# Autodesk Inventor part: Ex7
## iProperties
Author: Administrator
Created: 2001-01
Part Number: Ex7
Document SubType Name: Modeling
Designer: Administrator
Control State: 0
Master: False
Checked Out: False
PropertySet Name: Design Tracking Control
Shininess: 0.0
PropertySet Name: _Private Model Information
Density: 0.0
Volumn: 0.0
Area: 0.0
PropertySet Name: Model Information
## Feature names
1. Extrusion1
2. Extrusion2
3. Fillet1
4. Hole1
